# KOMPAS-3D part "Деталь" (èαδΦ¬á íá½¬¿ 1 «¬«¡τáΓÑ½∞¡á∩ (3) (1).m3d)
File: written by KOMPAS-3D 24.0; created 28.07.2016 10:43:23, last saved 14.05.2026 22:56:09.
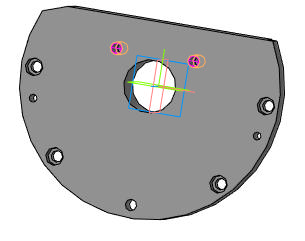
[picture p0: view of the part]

Document properties: Полное имя файла: E:\test_kompas\all_v22\Крышка балки 1 окончательная (3) (1).m3d

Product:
- Part/product: Деталь
    Масса: 9.688835
- Part/product: Деталь  | designation 01
    Масса: 9.688835

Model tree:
1. Эскиз:1
2. Операция выдавливания:1
     Расстояние 1 = 40
3. Эскиз:2  (with: Грань.Операция выдавливания:1)
4. Элемент выдавливания:2
     Расстояние 2 = 20
5. Эскиз:13  (with: Грань.Операция выдавливания:1)
6. Элемент выдавливания:5
     Расстояние 2 = 40
7. Эскиз:14  (with: Грань.Операция выдавливания:1)
8. Эскиз:15  (with: Грань.Операция выдавливания:1, Ребро.Элемент выдавливания:2)
9. Элемент выдавливания:6
     Расстояние 2 = 40
10. Эскиз:16  (with: Грань.Операция выдавливания:1, Ребро.Элемент выдавливания:2)
11. Элемент выдавливания:7
     Расстояние 2 = 11
12. Отверстие:3  (with: Грань.Операция выдавливания:1, Ребро.Операция выдавливания:1)  (labels: M12)
     Глубина выреза = 30; Диаметр отверстия = 10.1056; Угол конуса дна = 118; Расстояние 1 = 31; Расстояние 2 = 46.4075
13. M12  (with: Грань.Отверстие:3, Грань.Операция выдавливания:1, Операция выдавливания:1)  (labels: M12; cil0_24705-2004 coarse)
     Длина резьбы = 25; Шаг резьбы = 1.75; Номинальный диаметр резьбы = 12
14. Отверстие:4  (with: Грань.Операция выдавливания:1, Ребро.Операция выдавливания:1, M12, Грань.Отверстие:4, Операция выдавливания:1)  (labels: M12; cil0_24705-2004 coarse)
     Глубина выреза = 30; Диаметр отверстия = 10.1056; Угол конуса дна = 118; Расстояние 1 = 31; Расстояние 2 = 70.8326; Длина резьбы = 25; Шаг резьбы = 1.75; Номинальный диаметр резьбы = 12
